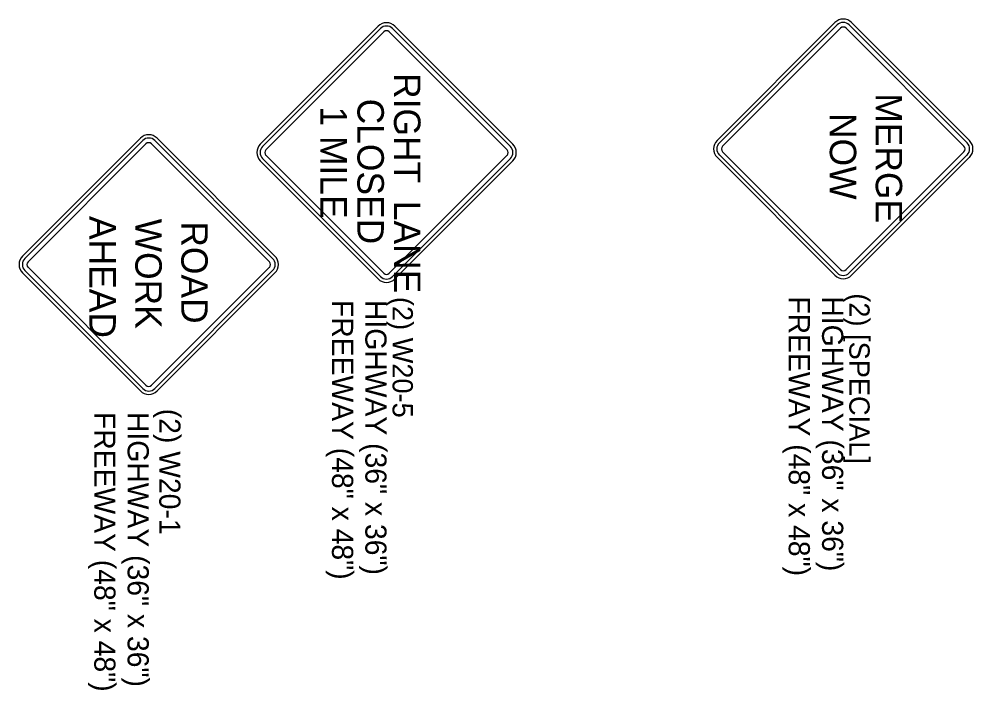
# Model space of a CAD drawing. Extents: x 1930579 to 1937521, y 596183 to 597599.
# Drawn here: x 1933772.6 to 1934043.2, y 596930.8 to 597120.9 of the extents above; entities that cross this region are included whole.
import ezdxf

# ---------------------------------------------------------------- set-up
doc = ezdxf.new("R2010")
doc.units = 0
doc.layers.add('P_TC_Signs_Temporary', color=7, linetype='Continuous')
doc.layers.add('R_Annotation', color=7, linetype='Continuous')

msp = doc.modelspace()

# ---------------------------------------------------------------- linework, layer by layer
at = {"layer": 'P_TC_Signs_Temporary'}
for p, q in [((1933841.06, 597085.51), (1933874.47, 597118.92)), ((1933841.72, 597084.85), (1933875.13, 597118.26)), ((1933878.58, 597118.26), (1933911.99, 597084.85)), ((1933879.24, 597118.92), (1933912.65, 597085.51)), ((1933970.59, 597086.53), (1934004, 597119.94)), ((1933971.25, 597085.87), (1934004.66, 597119.28)), ((1933972.18, 597084.94), (1934005.59, 597118.35)), ((1934007.18, 597118.35), (1934040.59, 597084.94)), ((1934008.11, 597119.28), (1934041.52, 597085.87)), ((1934008.77, 597119.94), (1934042.18, 597086.53)), ((1933842.65, 597083.92), (1933876.06, 597117.33)), ((1933877.65, 597117.33), (1933911.06, 597083.92)), ((1933773.63, 597053.77), (1933807.04, 597087.18)), ((1933774.29, 597053.11), (1933807.7, 597086.52)), ((1933775.22, 597052.18), (1933808.63, 597085.59)), ((1933810.22, 597085.59), (1933843.63, 597052.18)), ((1933811.15, 597086.52), (1933844.56, 597053.11)), ((1933811.81, 597087.18), (1933845.22, 597053.77)), ((1934005.59, 597049.94), (1933972.18, 597083.35)), ((1934040.59, 597083.35), (1934007.18, 597049.94)), ((1933874.47, 597047.33), (1933841.06, 597080.74)), ((1933875.13, 597047.99), (1933841.72, 597081.4)), ((1933876.06, 597048.92), (1933842.65, 597082.33)), ((1933911.06, 597082.33), (1933877.65, 597048.92)), ((1933911.99, 597081.4), (1933878.58, 597047.99)), ((1933912.65, 597080.74), (1933879.24, 597047.33)), ((1934004, 597048.35), (1933970.59, 597081.76)), ((1934004.66, 597049.01), (1933971.25, 597082.42)), ((1934041.52, 597082.42), (1934008.11, 597049.01)), ((1934042.18, 597081.76), (1934008.77, 597048.35)), ((1933808.63, 597017.18), (1933775.22, 597050.59)), ((1933843.63, 597050.59), (1933810.22, 597017.18)), ((1933807.04, 597015.58), (1933773.63, 597049)), ((1933807.7, 597016.25), (1933774.29, 597049.66)), ((1933844.56, 597049.66), (1933811.15, 597016.25)), ((1933845.22, 597049), (1933811.81, 597015.58))]:
    msp.add_line(p, q, dxfattribs=at)
for centre, radius, start, end in [((1934006.39, 597117.56), 3.37, 45, 135), ((1933876.85, 597116.53), 3.37, 45, 135), ((1933876.85, 597116.53), 2.44, 45, 135), ((1934006.39, 597117.56), 2.44, 45, 135), ((1934006.39, 597117.56), 1.12, 45, 135), ((1933876.85, 597116.53), 1.12, 45, 135), ((1933809.42, 597084.79), 3.37, 45, 135), ((1933809.42, 597084.79), 2.44, 45, 135), ((1933809.42, 597084.79), 1.12, 45, 135), ((1933843.44, 597083.12), 3.37, 135, 225), ((1933910.26, 597083.12), 3.38, 315, 45), ((1933972.98, 597084.14), 3.37, 135, 225), ((1933972.98, 597084.14), 2.44, 135, 225), ((1934039.8, 597084.14), 2.44, 315, 45), ((1934039.8, 597084.14), 3.38, 315, 45), ((1933843.44, 597083.12), 2.44, 135, 225), ((1933843.44, 597083.12), 1.13, 135, 225), ((1933910.26, 597083.12), 1.13, 315, 45), ((1933910.26, 597083.12), 2.44, 315, 45), ((1933972.98, 597084.14), 1.13, 135, 225), ((1934039.8, 597084.14), 1.13, 315, 45), ((1933776.01, 597051.38), 3.37, 135, 225), ((1933776.01, 597051.38), 2.44, 135, 225), ((1933842.83, 597051.38), 2.44, 315, 45), ((1933842.83, 597051.38), 3.38, 315, 45), ((1933776.01, 597051.38), 1.13, 135, 225), ((1933842.83, 597051.38), 1.13, 315, 45), ((1933876.85, 597049.71), 2.44, 225, 315), ((1933876.85, 597049.71), 1.12, 225, 315), ((1934006.39, 597050.73), 3.38, 225, 315), ((1934006.39, 597050.73), 2.44, 225, 315), ((1934006.39, 597050.73), 1.12, 225, 315), ((1933876.85, 597049.71), 3.38, 225, 315), ((1933809.42, 597017.97), 3.38, 225, 315), ((1933809.42, 597017.97), 2.44, 225, 315), ((1933809.42, 597017.97), 1.12, 225, 315)]:
    msp.add_arc(centre, radius, start, end, dxfattribs=at)

# ---------------------------------------------------------------- texts
for s, p in [('RIGHT\u2002LANE', (1933878.98, 597105.64)), ('MERGE', (1934015.6, 597099.9)), ('CLOSED', (1933868.6, 597098.38)), ('1 MILE', (1933858.1, 597096.17)), ('NOW', (1934002.58, 597094.31)), (' AHEAD ', (1933792.59, 597067.92)), ('WORK', (1933805.61, 597064.37)), (' ROAD ', (1933818.64, 597066.4))]:
    msp.add_text(s, height=7.5, rotation=270, dxfattribs=at).set_placement(p)
at = {"layer": 'R_Annotation'}
for s, height, p in [('(2) [SPECIAL]', 5.76, (1934008.11, 597043.22)), ('FREEWAY (48" x 48")', 6, (1933861.4, 597041.34)), ('HIGHWAY (36" x 36")', 6, (1933870.85, 597041.34)), ('(2) W20-5', 5.76, (1933878.57, 597042.2)), ('FREEWAY (48" x 48")', 6, (1933990.93, 597042.36)), ('HIGHWAY (36" x 36")', 6, (1934000.39, 597042.36)), ('(2) W20-1', 6, (1933812.41, 597010.51)), ('FREEWAY (48" x 48")', 6, (1933793.97, 597009.6)), ('HIGHWAY (36" x 36")', 6, (1933803.42, 597009.6))]:
    msp.add_text(s, height=height, rotation=270, dxfattribs=at).set_placement(p)

doc.saveas('drawing.dxf')
